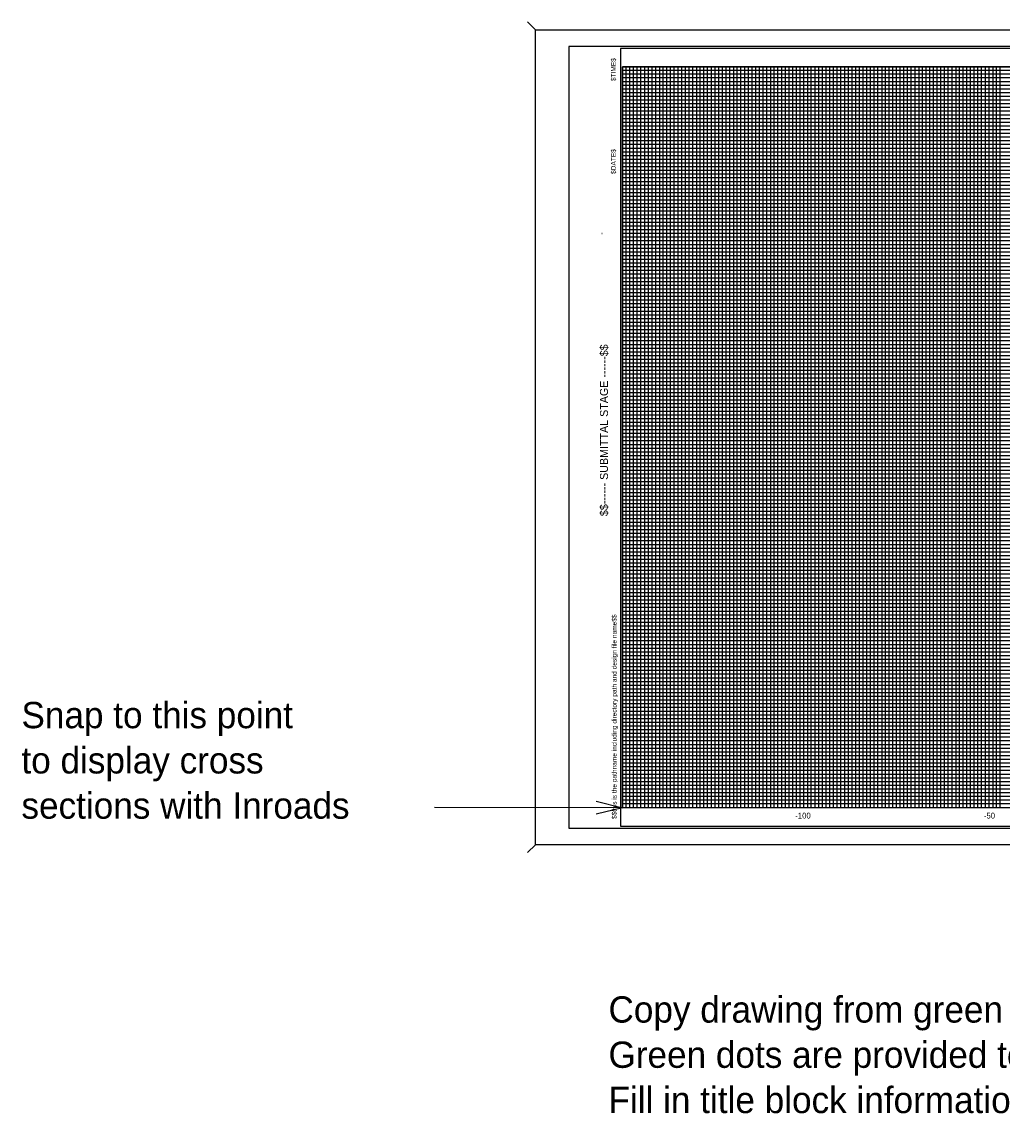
# Model space of a CAD drawing. Extents: x -139 to 18809, y -75 to 270.
# Drawn here: x -138.7 to 126, y -74.6 to 222.1 of the extents above; entities that cross this region are included whole.
import ezdxf

# ---------------------------------------------------------------- set-up
doc = ezdxf.new("R2010")
doc.units = 0
for name, color, linetype in [('Construction Class', 7, 'Continuous'), ('File Info', 7, 'Continuous'), ('Grid', 7, 'Continuous'), ('Plot Border', 7, 'Continuous'), ('Sheet Border', 7, 'Continuous')]:
    doc.layers.add(name, color=color, linetype=linetype)

msp = doc.modelspace()

# ---------------------------------------------------------------- linework, layer by layer
at = {"layer": 'Construction Class'}
msp.add_line((18, 165), (18, 165), dxfattribs=at)
at = {"layer": 'File Info'}
for p, q in [((23.5, 10), (-27.24, 10.03)), ((23, 5), (23, 5))]:
    msp.add_line(p, q, dxfattribs=at)
msp.add_lwpolyline([(16.4, 11.78), (23.5, 10), (16.4, 8.23)], dxfattribs=at)
at = {"layer": 'Grid'}
for p, q in [((23.5, 210), (23.5, 10)), ((23.5, 210), (23.5, 210)), ((323.5, 210), (23.5, 210)), ((323.5, 209), (23.5, 209)), ((323.5, 208), (23.5, 208)), ((24.5, 10), (24.5, 210)), ((25.5, 10), (25.5, 210)), ((26.5, 10), (26.5, 210)), ((27.5, 10), (27.5, 210)), ((28.5, 10), (28.5, 210)), ((29.5, 10), (29.5, 210)), ((30.5, 10), (30.5, 210)), ((31.5, 10), (31.5, 210)), ((32.5, 10), (32.5, 210)), ((33.5, 210), (33.5, 10)), ((34.5, 10), (34.5, 210)), ((35.5, 10), (35.5, 210)), ((36.5, 10), (36.5, 210)), ((37.5, 10), (37.5, 210)), ((38.5, 10), (38.5, 210)), ((39.5, 10), (39.5, 210)), ((40.5, 10), (40.5, 210)), ((41.5, 10), (41.5, 210)), ((42.5, 10), (42.5, 210)), ((43.5, 210), (43.5, 10)), ((44.5, 10), (44.5, 210)), ((45.5, 10), (45.5, 210)), ((46.5, 10), (46.5, 210)), ((47.5, 10), (47.5, 210)), ((48.5, 10), (48.5, 210)), ((49.5, 10), (49.5, 210)), ((50.5, 10), (50.5, 210)), ((51.5, 10), (51.5, 210)), ((52.5, 10), (52.5, 210)), ((53.5, 210), (53.5, 10)), ((54.5, 10), (54.5, 210)), ((55.5, 10), (55.5, 210)), ((56.5, 10), (56.5, 210)), ((57.5, 10), (57.5, 210)), ((58.5, 10), (58.5, 210)), ((59.5, 10), (59.5, 210)), ((60.5, 10), (60.5, 210)), ((61.5, 10), (61.5, 210)), ((62.5, 10), (62.5, 210)), ((63.5, 210), (63.5, 10)), ((64.5, 10), (64.5, 210)), ((65.5, 10), (65.5, 210)), ((66.5, 10), (66.5, 210)), ((67.5, 10), (67.5, 210)), ((68.5, 10), (68.5, 210)), ((69.5, 10), (69.5, 210)), ((70.5, 10), (70.5, 210)), ((71.5, 10), (71.5, 210)), ((72.5, 10), (72.5, 210)), ((73.5, 210), (73.5, 10)), ((74.5, 10), (74.5, 210)), ((75.5, 10), (75.5, 210)), ((76.5, 10), (76.5, 210)), ((77.5, 10), (77.5, 210)), ((78.5, 10), (78.5, 210)), ((79.5, 10), (79.5, 210)), ((80.5, 10), (80.5, 210)), ((81.5, 10), (81.5, 210)), ((82.5, 10), (82.5, 210)), ((83.5, 210), (83.5, 10)), ((84.5, 10), (84.5, 210)), ((85.5, 10), (85.5, 210)), ((86.5, 10), (86.5, 210)), ((87.5, 10), (87.5, 210)), ((88.5, 10), (88.5, 210)), ((89.5, 10), (89.5, 210)), ((90.5, 10), (90.5, 210)), ((91.5, 10), (91.5, 210)), ((92.5, 10), (92.5, 210)), ((93.5, 210), (93.5, 10)), ((94.5, 10), (94.5, 210)), ((95.5, 10), (95.5, 210)), ((96.5, 10), (96.5, 210)), ((97.5, 10), (97.5, 210)), ((98.5, 10), (98.5, 210)), ((99.5, 10), (99.5, 210)), ((100.5, 10), (100.5, 210)), ((101.5, 10), (101.5, 210)), ((102.5, 10), (102.5, 210)), ((103.5, 210), (103.5, 10)), ((104.5, 10), (104.5, 210)), ((105.5, 10), (105.5, 210)), ((106.5, 10), (106.5, 210)), ((107.5, 10), (107.5, 210)), ((108.5, 10), (108.5, 210)), ((109.5, 10), (109.5, 210)), ((110.5, 10), (110.5, 210)), ((111.5, 10), (111.5, 210)), ((112.5, 10), (112.5, 210)), ((113.5, 210), (113.5, 10)), ((114.5, 10), (114.5, 210)), ((115.5, 10), (115.5, 210)), ((116.5, 10), (116.5, 210)), ((117.5, 10), (117.5, 210)), ((118.5, 10), (118.5, 210)), ((119.5, 10), (119.5, 210)), ((120.5, 10), (120.5, 210)), ((121.5, 10), (121.5, 210)), ((122.5, 10), (122.5, 210)), ((123.5, 210), (123.5, 10)), ((124.5, 10), (124.5, 210)), ((125.5, 10), (125.5, 210)), ((323.5, 207), (23.5, 207)), ((323.5, 206), (23.5, 206)), ((323.5, 205), (23.5, 205)), ((323.5, 204), (23.5, 204)), ((323.5, 203), (23.5, 203)), ((323.5, 202), (23.5, 202)), ((323.5, 201), (23.5, 201)), ((323.5, 200), (23.5, 200)), ((323.5, 199), (23.5, 199)), ((323.5, 198), (23.5, 198)), ((323.5, 197), (23.5, 197)), ((323.5, 196), (23.5, 196)), ((323.5, 195), (23.5, 195)), ((323.5, 194), (23.5, 194)), ((323.5, 193), (23.5, 193)), ((323.5, 192), (23.5, 192)), ((323.5, 191), (23.5, 191)), ((323.5, 190), (23.5, 190)), ((323.5, 189), (23.5, 189)), ((323.5, 188), (23.5, 188)), ((323.5, 187), (23.5, 187)), ((323.5, 186), (23.5, 186)), ((323.5, 185), (23.5, 185)), ((323.5, 184), (23.5, 184)), ((323.5, 183), (23.5, 183)), ((323.5, 182), (23.5, 182)), ((323.5, 181), (23.5, 181)), ((323.5, 180), (23.5, 180)), ((323.5, 179), (23.5, 179)), ((323.5, 178), (23.5, 178)), ((323.5, 177), (23.5, 177)), ((323.5, 176), (23.5, 176)), ((323.5, 175), (23.5, 175)), ((323.5, 174), (23.5, 174)), ((323.5, 173), (23.5, 173)), ((323.5, 172), (23.5, 172)), ((323.5, 171), (23.5, 171)), ((323.5, 170), (23.5, 170)), ((323.5, 169), (23.5, 169)), ((323.5, 168), (23.5, 168)), ((323.5, 167), (23.5, 167)), ((323.5, 166), (23.5, 166)), ((323.5, 165), (23.5, 165)), ((323.5, 164), (23.5, 164)), ((323.5, 163), (23.5, 163)), ((323.5, 162), (23.5, 162)), ((323.5, 161), (23.5, 161)), ((323.5, 160), (23.5, 160)), ((323.5, 159), (23.5, 159)), ((323.5, 158), (23.5, 158)), ((323.5, 157), (23.5, 157)), ((323.5, 156), (23.5, 156)), ((323.5, 155), (23.5, 155)), ((323.5, 154), (23.5, 154)), ((323.5, 153), (23.5, 153)), ((323.5, 152), (23.5, 152)), ((323.5, 151), (23.5, 151)), ((323.5, 150), (23.5, 150)), ((323.5, 149), (23.5, 149)), ((323.5, 148), (23.5, 148)), ((323.5, 147), (23.5, 147)), ((323.5, 146), (23.5, 146)), ((323.5, 145), (23.5, 145)), ((323.5, 144), (23.5, 144)), ((323.5, 143), (23.5, 143)), ((323.5, 142), (23.5, 142)), ((323.5, 141), (23.5, 141)), ((323.5, 140), (23.5, 140)), ((323.5, 139), (23.5, 139)), ((323.5, 138), (23.5, 138)), ((323.5, 137), (23.5, 137)), ((323.5, 136), (23.5, 136)), ((323.5, 135), (23.5, 135)), ((323.5, 134), (23.5, 134)), ((323.5, 133), (23.5, 133)), ((323.5, 132), (23.5, 132)), ((323.5, 131), (23.5, 131)), ((323.5, 130), (23.5, 130)), ((323.5, 129), (23.5, 129)), ((323.5, 128), (23.5, 128)), ((323.5, 127), (23.5, 127)), ((323.5, 126), (23.5, 126)), ((323.5, 125), (23.5, 125)), ((323.5, 124), (23.5, 124)), ((323.5, 123), (23.5, 123)), ((323.5, 122), (23.5, 122)), ((323.5, 121), (23.5, 121)), ((323.5, 120), (23.5, 120)), ((323.5, 119), (23.5, 119)), ((323.5, 118), (23.5, 118)), ((323.5, 117), (23.5, 117)), ((323.5, 116), (23.5, 116)), ((323.5, 115), (23.5, 115)), ((323.5, 114), (23.5, 114)), ((323.5, 113), (23.5, 113)), ((323.5, 112), (23.5, 112)), ((323.5, 111), (23.5, 111)), ((323.5, 110), (23.5, 110)), ((323.5, 109), (23.5, 109)), ((323.5, 108), (23.5, 108)), ((323.5, 107), (23.5, 107)), ((323.5, 106), (23.5, 106)), ((323.5, 105), (23.5, 105)), ((323.5, 104), (23.5, 104)), ((323.5, 103), (23.5, 103)), ((323.5, 102), (23.5, 102)), ((323.5, 101), (23.5, 101)), ((323.5, 100), (23.5, 100)), ((323.5, 99), (23.5, 99)), ((323.5, 98), (23.5, 98)), ((323.5, 97), (23.5, 97)), ((323.5, 96), (23.5, 96)), ((323.5, 95), (23.5, 95)), ((323.5, 94), (23.5, 94)), ((323.5, 93), (23.5, 93)), ((323.5, 92), (23.5, 92)), ((323.5, 91), (23.5, 91)), ((323.5, 90), (23.5, 90)), ((323.5, 89), (23.5, 89)), ((323.5, 88), (23.5, 88)), ((323.5, 87), (23.5, 87)), ((323.5, 86), (23.5, 86)), ((323.5, 85), (23.5, 85)), ((323.5, 84), (23.5, 84)), ((323.5, 83), (23.5, 83)), ((323.5, 82), (23.5, 82)), ((323.5, 81), (23.5, 81)), ((323.5, 80), (23.5, 80)), ((323.5, 79), (23.5, 79)), ((323.5, 78), (23.5, 78)), ((323.5, 77), (23.5, 77)), ((323.5, 76), (23.5, 76)), ((323.5, 75), (23.5, 75)), ((323.5, 74), (23.5, 74)), ((323.5, 73), (23.5, 73)), ((323.5, 72), (23.5, 72)), ((323.5, 71), (23.5, 71)), ((323.5, 70), (23.5, 70)), ((323.5, 69), (23.5, 69)), ((323.5, 68), (23.5, 68)), ((323.5, 67), (23.5, 67)), ((323.5, 66), (23.5, 66)), ((323.5, 65), (23.5, 65)), ((323.5, 64), (23.5, 64)), ((323.5, 63), (23.5, 63)), ((323.5, 62), (23.5, 62)), ((323.5, 61), (23.5, 61)), ((323.5, 60), (23.5, 60)), ((323.5, 59), (23.5, 59)), ((323.5, 58), (23.5, 58)), ((323.5, 57), (23.5, 57)), ((323.5, 56), (23.5, 56)), ((323.5, 55), (23.5, 55)), ((323.5, 54), (23.5, 54)), ((323.5, 53), (23.5, 53)), ((323.5, 52), (23.5, 52)), ((323.5, 51), (23.5, 51)), ((323.5, 50), (23.5, 50)), ((323.5, 49), (23.5, 49)), ((323.5, 48), (23.5, 48)), ((323.5, 47), (23.5, 47)), ((323.5, 46), (23.5, 46)), ((323.5, 45), (23.5, 45)), ((323.5, 44), (23.5, 44)), ((323.5, 43), (23.5, 43)), ((323.5, 42), (23.5, 42)), ((323.5, 41), (23.5, 41)), ((323.5, 40), (23.5, 40)), ((323.5, 39), (23.5, 39)), ((323.5, 38), (23.5, 38)), ((323.5, 37), (23.5, 37)), ((323.5, 36), (23.5, 36)), ((323.5, 35), (23.5, 35)), ((323.5, 34), (23.5, 34)), ((323.5, 33), (23.5, 33)), ((323.5, 32), (23.5, 32)), ((323.5, 31), (23.5, 31)), ((323.5, 30), (23.5, 30)), ((323.5, 29), (23.5, 29)), ((323.5, 28), (23.5, 28)), ((323.5, 27), (23.5, 27)), ((323.5, 26), (23.5, 26)), ((323.5, 25), (23.5, 25)), ((323.5, 24), (23.5, 24)), ((323.5, 23), (23.5, 23)), ((323.5, 22), (23.5, 22)), ((323.5, 21), (23.5, 21)), ((323.5, 20), (23.5, 20)), ((323.5, 19), (23.5, 19)), ((323.5, 18), (23.5, 18)), ((323.5, 17), (23.5, 17)), ((323.5, 16), (23.5, 16)), ((323.5, 15), (23.5, 15)), ((323.5, 14), (23.5, 14)), ((323.5, 13), (23.5, 13)), ((323.5, 12), (23.5, 12)), ((323.5, 11), (23.5, 11)), ((323.5, 10), (23.5, 10))]:
    msp.add_line(p, q, dxfattribs=at)
msp.add_lwpolyline([(23.5, 210), (323.5, 210), (323.5, 10), (23.5, 10)], close=True, dxfattribs=at)
at = {"layer": 'Plot Border'}
for p, q in [((0, 220), (-2.12, 222.12)), ((0, 0), (-2.12, -2.12))]:
    msp.add_line(p, q, dxfattribs=at)
for points in [[(0, 220), (340, 220), (340, 0), (0, 0)], [(339, 215.5), (9, 215.5), (9, 4.5), (339, 4.5)]]:
    msp.add_lwpolyline(points, close=True, dxfattribs=at)
at = {"layer": 'Sheet Border'}
for p, q in [((338, 215), (23, 215)), ((23, 215), (23, 5)), ((23, 5), (338, 5))]:
    msp.add_line(p, q, dxfattribs=at)

# ---------------------------------------------------------------- texts
at = {"layer": 'File Info'}
for s, p in [('Snap to this point', (-138.81, 31.45)), ('to display cross', (-138.81, 19.23)), ('sections with Inroads', (-138.81, 7.02)), ("Copy drawing from green dot to green dot (380'). ", (19.72, -48.03)), ('Green dots are provided to maintain the correct spacing for InRoads preference files.  ', (19.72, -60.24)), ('Fill in title block information before copying drawing.  Number drawings starting with 401.', (19.72, -72.46))]:
    msp.add_text(s, height=7.096, dxfattribs=at).set_placement(p)
at = {"layer": 'Grid'}
for s, p in [('-100', (70.16, 7.07)), ('-50', (121.1, 7.07))]:
    msp.add_text(s, height=1.565, dxfattribs=at).set_placement(p)
at = {"layer": 'Plot Border'}
for s, height, p in [('$TIME$', 1.28, (21.69, 206.16)), ('$DATE$', 1.28, (21.69, 181.1)), ('$$------ SUBMITTAL STAGE ------$$', 2.16, (19.58, 88.71)), ('$$this is the pathname including directory path and design file name$$', 1.28, (21.91, 6.95))]:
    msp.add_text(s, height=height, rotation=90, dxfattribs=at).set_placement(p)
at = {"layer": 'Sheet Border'}
msp.add_text('X', height=0.5, dxfattribs=at).set_placement((17.73, 164.75))

doc.saveas('drawing.dxf')
